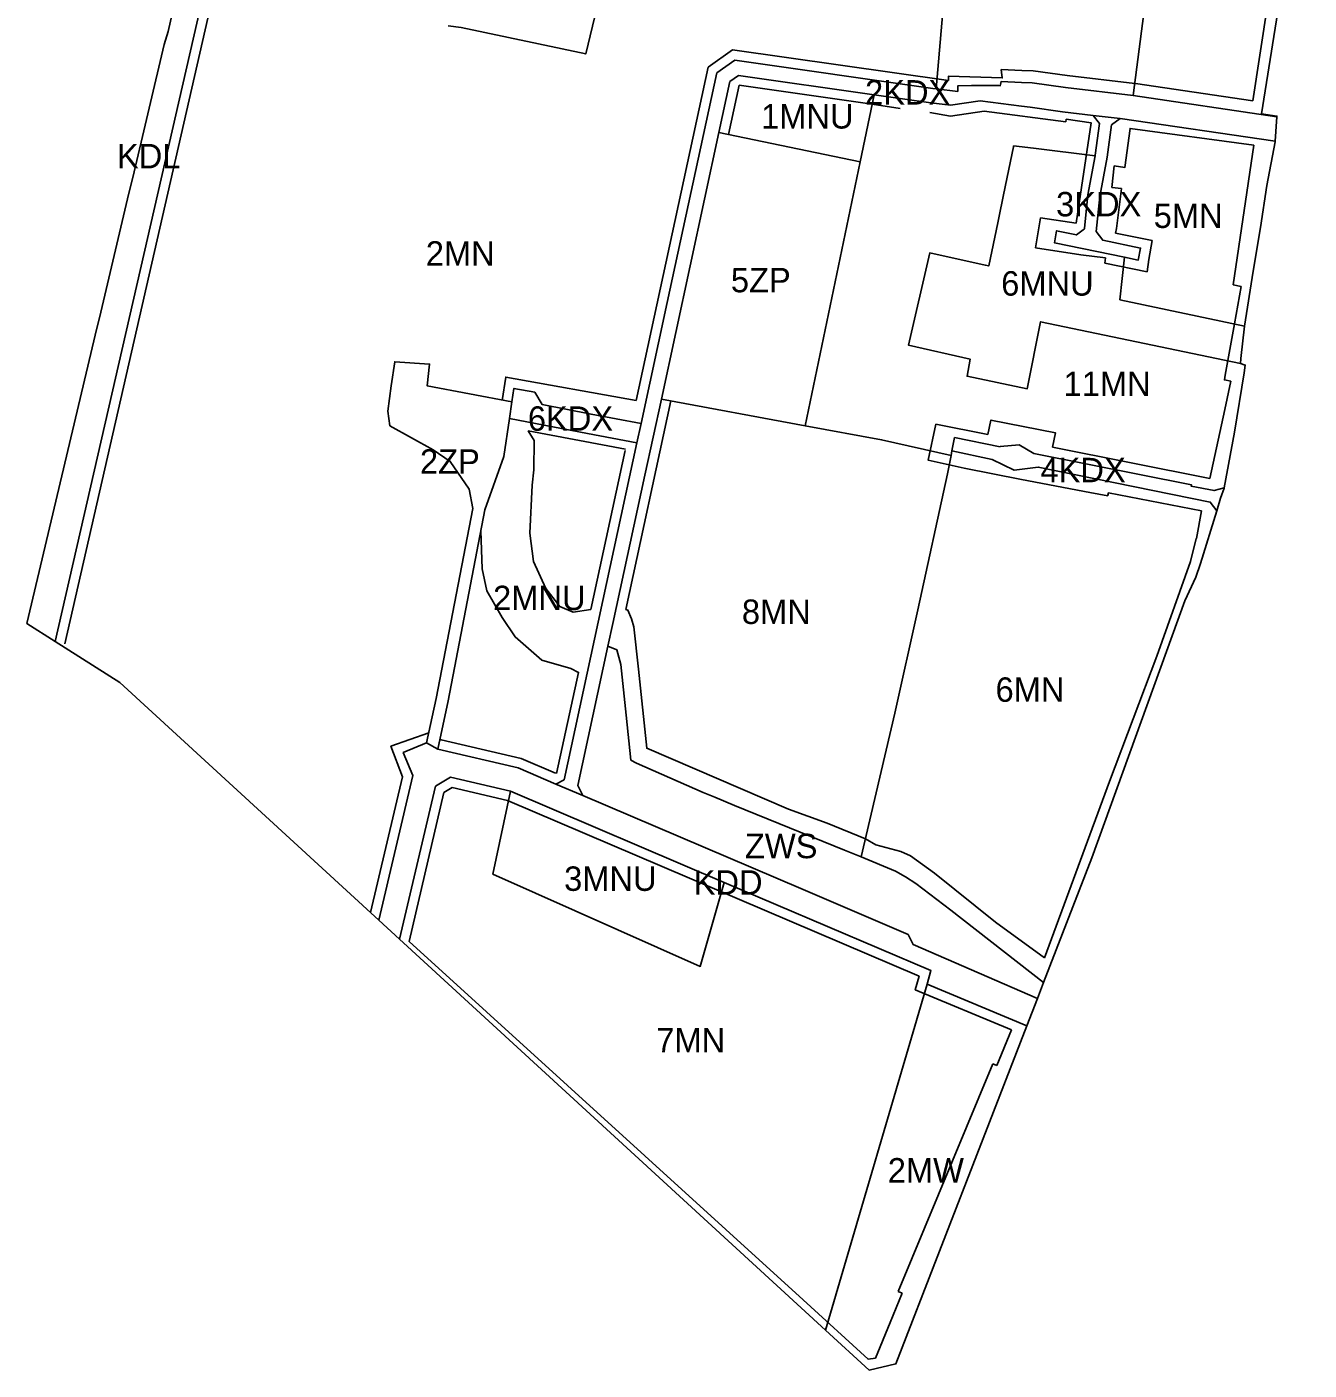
# Model space of a CAD drawing. Extents: x 7419547 to 7422145, y 5541032 to 5541974.
# Drawn here: x 7420351 to 7420876, y 5541032 to 5541582 of the extents above; entities that cross this region are included whole.
import ezdxf

# ---------------------------------------------------------------- set-up
doc = ezdxf.new("R2010")
doc.units = 0
for name, color, linetype in [('linie_rozgraniczajace', 7, 'Continuous'), ('linie_zabudowy_nieprzekraczalne', 7, 'Continuous'), ('oznaczenia_przeznaczen', 7, 'Continuous')]:
    doc.layers.add(name, color=color, linetype=linetype)

msp = doc.modelspace()

# ---------------------------------------------------------------- linework, layer by layer
at = {"layer": 'linie_rozgraniczajace'}
for points in [[(7420734.65, 5541689.59), (7420736.72, 5541689.3), (7420800.6, 5541672.71), (7420818.6, 5541669.11), (7420803.79, 5541554.09), (7420803.78, 5541554.09), (7420776.06, 5541557.45), (7420762.38, 5541559.34), (7420757.99, 5541559.45), (7420749.65, 5541559.87), (7420749.32, 5541558.18), (7420748.75, 5541558.22), (7420737.58, 5541558.22), (7420731.97, 5541558.15), (7420731.89, 5541555.85), (7420723.05, 5541556.92), (7420726.09, 5541591.68), (7420728.7, 5541621.57)], [(7420819.8, 5541678.4), (7420875.82, 5541668.83), (7420874.09, 5541658.03), (7420856.27, 5541546.71), (7420862.63, 5541545.75), (7420862.61, 5541545.48), (7420803.79, 5541554.09), (7420818.6, 5541669.11)], [(7420640.62, 5541568.67), (7420721.7, 5541557.08), (7420723.05, 5541556.92), (7420731.89, 5541555.85), (7420731.97, 5541558.15), (7420737.58, 5541558.22), (7420748.75, 5541558.22), (7420749.32, 5541558.18), (7420749.65, 5541559.87), (7420757.99, 5541559.45), (7420762.38, 5541559.34), (7420776.06, 5541557.45), (7420803.78, 5541554.09), (7420803.79, 5541554.09), (7420862.61, 5541545.48), (7420861.89, 5541535.48), (7420798.37, 5541544.78), (7420787.34, 5541546.01), (7420774.78, 5541547.53), (7420761.56, 5541549.36), (7420758.03, 5541549.77), (7420741.04, 5541552.02), (7420728.98, 5541550.16), (7420720.92, 5541551.13), (7420697.59, 5541554.47), (7420642.13, 5541562.39), (7420638.58, 5541559.88), (7420634.06, 5541538.95), (7420610.47, 5541429.83), (7420603.72, 5541398.61), (7420590.58, 5541337.83), (7420588.59, 5541328.63), (7420576.24, 5541271.46), (7420578.36, 5541267.35), (7420567.22, 5541272.1), (7420570.62, 5541273.86), (7420600.46, 5541411.93), (7420602.15, 5541419.75), (7420612.87, 5541469.33), (7420633.21, 5541563.43)], [(7420642.13, 5541562.39), (7420697.59, 5541554.47), (7420691.91, 5541526.98), (7420634.06, 5541538.95), (7420638.58, 5541559.88)], [(7420697.59, 5541554.47), (7420720.92, 5541551.13), (7420728.98, 5541550.16), (7420741.04, 5541552.02), (7420758.03, 5541549.77), (7420761.56, 5541549.36), (7420774.78, 5541547.53), (7420787.34, 5541546.01), (7420789.91, 5541542.68), (7420788.16, 5541529.73), (7420788.12, 5541529.49), (7420762.87, 5541532.52), (7420754.78, 5541533.48), (7420754.71, 5541533.12), (7420751.45, 5541517.47), (7420749.08, 5541506.07), (7420748.24, 5541502.03), (7420744.56, 5541484.37), (7420743.16, 5541484.68), (7420720.4, 5541489.65), (7420711.69, 5541451.89), (7420736.95, 5541446.16), (7420735.7, 5541439.12), (7420760.34, 5541434.06), (7420765.8, 5541461.49), (7420847.67, 5541444.42), (7420849.68, 5541443.73), (7420849.18, 5541440.56), (7420845.31, 5541416.26), (7420841.08, 5541393.47), (7420836.87, 5541392.29), (7420827.49, 5541394.16), (7420827.64, 5541394.62), (7420762.99, 5541407.51), (7420757.09, 5541411.02), (7420749.25, 5541410.34), (7420749.23, 5541410.25), (7420730.58, 5541414.03), (7420729.53, 5541408.63), (7420729.15, 5541406.72), (7420700.66, 5541413.11), (7420669.4, 5541418.9), (7420691.91, 5541526.98)], [(7420787.34, 5541546.01), (7420798.37, 5541544.78), (7420794.88, 5541542.08), (7420793.1, 5541528.95), (7420790.14, 5541512.76), (7420788.64, 5541498.43), (7420791.27, 5541494.84), (7420806.81, 5541491.64), (7420805.8, 5541486.74), (7420800.14, 5541487.91), (7420771.45, 5541493.82), (7420772.38, 5541498.74), (7420780.47, 5541497.07), (7420783.26, 5541499.11), (7420783.72, 5541499.45), (7420783.74, 5541499.63), (7420785.19, 5541513.47), (7420788.12, 5541529.49), (7420788.16, 5541529.73), (7420789.91, 5541542.68)], [(7420798.37, 5541544.78), (7420861.89, 5541535.48), (7420861.89, 5541535.44), (7420861.87, 5541535.22), (7420858.5, 5541517.3), (7420855.86, 5541500.15), (7420852.9, 5541482.22), (7420849.37, 5541459.72), (7420798.31, 5541470.47), (7420800.14, 5541487.91), (7420805.8, 5541486.74), (7420806.81, 5541491.64), (7420791.27, 5541494.84), (7420788.64, 5541498.43), (7420790.14, 5541512.76), (7420793.1, 5541528.95), (7420794.88, 5541542.08)], [(7420634.06, 5541538.95), (7420691.91, 5541526.98), (7420669.4, 5541418.9), (7420610.47, 5541429.83)], [(7420783.74, 5541499.63), (7420783.72, 5541499.45), (7420783.26, 5541499.11), (7420780.47, 5541497.07), (7420772.38, 5541498.74), (7420771.45, 5541493.82), (7420800.14, 5541487.91), (7420798.31, 5541470.47), (7420849.37, 5541459.72), (7420847.89, 5541446.41), (7420847.67, 5541444.42), (7420765.8, 5541461.49), (7420760.34, 5541434.06), (7420735.7, 5541439.12), (7420736.95, 5541446.16), (7420711.69, 5541451.89), (7420720.4, 5541489.65), (7420743.16, 5541484.68), (7420744.56, 5541484.37), (7420748.24, 5541502.03), (7420749.08, 5541506.07), (7420751.45, 5541517.47), (7420754.71, 5541533.12), (7420754.78, 5541533.48), (7420762.87, 5541532.52), (7420788.12, 5541529.49), (7420785.19, 5541513.47)], [(7420531.82, 5541392.96), (7420524.02, 5541404.24), (7420517.07, 5541409.04), (7420499.2, 5541418.86), (7420498.4, 5541424.9), (7420499.87, 5541435.22), (7420501.28, 5541445.08), (7420515.52, 5541444.16), (7420514.59, 5541435.22), (7420549.28, 5541428.69), (7420548.27, 5541421.78), (7420546, 5541406.31), (7420538.2, 5541384.45), (7420523.2, 5541306.2), (7420518.88, 5541286.38), (7420514.32, 5541288.95), (7420518.3, 5541307.21), (7420533.2, 5541384.96)], [(7420550.08, 5541434.14), (7420558.59, 5541432.62), (7420561.7, 5541427.57), (7420581.7, 5541423.6), (7420602.15, 5541419.75), (7420600.46, 5541411.93), (7420580.22, 5541415.74), (7420548.27, 5541421.78), (7420549.28, 5541428.69)], [(7420610.47, 5541429.83), (7420669.4, 5541418.9), (7420700.66, 5541413.11), (7420729.15, 5541406.72), (7420727.65, 5541399.12), (7420715.58, 5541343.49), (7420706.13, 5541301.09), (7420692.32, 5541242.22), (7420685.46, 5541245.07), (7420640.5, 5541263.37), (7420632.37, 5541266.67), (7420627.59, 5541268.61), (7420600.24, 5541280.68), (7420597.97, 5541281.9), (7420596.02, 5541300.29), (7420594.64, 5541313.34), (7420594.64, 5541313.34), (7420593.83, 5541321.06), (7420592.23, 5541327.11), (7420588.59, 5541328.63), (7420590.58, 5541337.83), (7420603.72, 5541398.61)], [(7420548.27, 5541421.78), (7420580.22, 5541415.74), (7420600.46, 5541411.93), (7420570.62, 5541273.86), (7420567.22, 5541272.1), (7420551.81, 5541278.68), (7420518.88, 5541286.38), (7420523.2, 5541306.2), (7420538.2, 5541384.45), (7420546, 5541406.31)], [(7420730.58, 5541414.03), (7420749.23, 5541410.25), (7420749.25, 5541410.34), (7420757.09, 5541411.02), (7420762.99, 5541407.51), (7420827.64, 5541394.62), (7420827.49, 5541394.16), (7420836.87, 5541392.29), (7420841.08, 5541393.47), (7420841.06, 5541393.36), (7420839.46, 5541389.21), (7420837.97, 5541383.96), (7420835.3, 5541387.58), (7420764.83, 5541401.93), (7420755.01, 5541400.62), (7420745.93, 5541405.06), (7420729.53, 5541408.63)], [(7420729.53, 5541408.63), (7420745.93, 5541405.06), (7420755.01, 5541400.62), (7420764.83, 5541401.93), (7420835.3, 5541387.58), (7420837.97, 5541383.96), (7420831.3, 5541362.47), (7420829.36, 5541356.9), (7420824.9, 5541347.17), (7420786.83, 5541241.86), (7420767.06, 5541190.8), (7420728.99, 5541220.4), (7420714.71, 5541231.31), (7420710.49, 5541234.08), (7420706.35, 5541236.39), (7420692.32, 5541242.22), (7420706.13, 5541301.09), (7420715.58, 5541343.49), (7420727.65, 5541399.12), (7420729.15, 5541406.72)], [(7420588.59, 5541328.63), (7420592.23, 5541327.11), (7420593.83, 5541321.06), (7420594.64, 5541313.34), (7420594.64, 5541313.34), (7420596.02, 5541300.29), (7420597.97, 5541281.9), (7420600.24, 5541280.68), (7420627.59, 5541268.61), (7420632.37, 5541266.67), (7420640.5, 5541263.37), (7420685.46, 5541245.07), (7420692.32, 5541242.22), (7420706.35, 5541236.39), (7420710.49, 5541234.08), (7420714.71, 5541231.31), (7420728.99, 5541220.4), (7420767.06, 5541190.8), (7420764.53, 5541184.26), (7420740.6, 5541194.63), (7420713.61, 5541206.34), (7420711.54, 5541210.53), (7420667.58, 5541229.28), (7420578.36, 5541267.35), (7420576.24, 5541271.46)], [(7420514.32, 5541288.95), (7420518.88, 5541286.38), (7420551.81, 5541278.68), (7420567.22, 5541272.1), (7420578.36, 5541267.35), (7420667.58, 5541229.28), (7420711.54, 5541210.53), (7420713.61, 5541206.34), (7420740.6, 5541194.63), (7420764.53, 5541184.26), (7420760.21, 5541173.11), (7420719.3, 5541190.15), (7420720.91, 5541195.66), (7420636.16, 5541231.82), (7420548.65, 5541269.15), (7420524.1, 5541274.89), (7420517.91, 5541271.21), (7420503.22, 5541208.56), (7420494.76, 5541216.31), (7420508.67, 5541275.63), (7420504.77, 5541284.96)], [(7420524.1, 5541274.89), (7420548.65, 5541269.15), (7420541.45, 5541235.24), (7420626.4, 5541197.41), (7420636.16, 5541231.82), (7420720.91, 5541195.66), (7420719.3, 5541190.15), (7420677.78, 5541048.37), (7420503.22, 5541208.56), (7420517.91, 5541271.21)], [(7420548.65, 5541269.15), (7420636.16, 5541231.82), (7420626.4, 5541197.41), (7420541.45, 5541235.24)], [(7420719.3, 5541190.15), (7420760.21, 5541173.11), (7420706.58, 5541034.58), (7420695.61, 5541032.01), (7420677.78, 5541048.37)]]:
    msp.add_lwpolyline(points, close=True, dxfattribs=at)
for points in [[(7420424.7, 5541603.62), (7420362.21, 5541330.48), (7420350.58, 5541337.88), (7420379.28, 5541458.82), (7420380.3, 5541463.13), (7420392.39, 5541514.09), (7420393.92, 5541520.52), (7420406.87, 5541575.07), (7420408.5, 5541580.32), (7420410.62, 5541590.07)], [(7420726.09, 5541591.68), (7420723.05, 5541556.92), (7420721.7, 5541557.08), (7420640.62, 5541568.67), (7420633.21, 5541563.43), (7420612.87, 5541469.33), (7420602.15, 5541419.75), (7420581.7, 5541423.6), (7420561.7, 5541427.57), (7420558.59, 5541432.62), (7420550.08, 5541434.14), (7420549.28, 5541428.69), (7420514.59, 5541435.22), (7420515.52, 5541444.16), (7420501.28, 5541445.08), (7420499.87, 5541435.22), (7420498.4, 5541424.9), (7420499.2, 5541418.86), (7420517.07, 5541409.04), (7420524.02, 5541404.24), (7420531.82, 5541392.96), (7420533.2, 5541384.96), (7420518.3, 5541307.21), (7420514.32, 5541288.95), (7420504.77, 5541284.96), (7420508.67, 5541275.63), (7420494.76, 5541216.31), (7420388.7, 5541313.64), (7420362.21, 5541330.48), (7420424.7, 5541603.62)], [(7420585, 5541594.08), (7420579.5, 5541571.17), (7420528.54, 5541582), (7420523.09, 5541582.75)], [(7420523.09, 5541582.75), (7420528.54, 5541582), (7420579.5, 5541571.17), (7420585, 5541594.08)]]:
    msp.add_lwpolyline(points, dxfattribs=at)
at = {"layer": 'linie_zabudowy_nieprzekraczalne'}
for points in [[(7420852.74, 5541551.98), (7420870.82, 5541669.68)], [(7420431.32, 5541614.61), (7420366.11, 5541329.59)], [(7420629.63, 5541565.79), (7420639.6, 5541572.85)], [(7420639.6, 5541572.85), (7420728.04, 5541560.34), (7420728.1, 5541562.09), (7420750.13, 5541561.36), (7420749.73, 5541564.87)], [(7420600.11, 5541429.24), (7420629.63, 5541565.79)], [(7420749.73, 5541564.87), (7420758.18, 5541564.45), (7420762.78, 5541564.33), (7420776.71, 5541562.41), (7420804.43, 5541559.05)], [(7420642.36, 5541558.43), (7420637.97, 5541538.14)], [(7420696.78, 5541550.54), (7420642.36, 5541558.43)], [(7420804.63, 5541559.02), (7420852.74, 5541551.98)], [(7420708.3, 5541548.88), (7420696.78, 5541550.54)], [(7420728.85, 5541545.75), (7420720.4, 5541547.17)], [(7420776.17, 5541543.33), (7420742.67, 5541547.77), (7420728.85, 5541545.75)], [(7420765.73, 5541504.1), (7420780.39, 5541501.88), (7420786.57, 5541542.91), (7420776.33, 5541544.44)], [(7420776.17, 5541543.33), (7420776.33, 5541544.44)], [(7420853.12, 5541533.8), (7420802.5, 5541540.65), (7420800.35, 5541524.72), (7420796.02, 5541525.29), (7420795.07, 5541516.49), (7420798.95, 5541516.02), (7420796.94, 5541499.65)], [(7420844.75, 5541476.54), (7420853.12, 5541533.8)], [(7420792.41, 5541487.6), (7420782.34, 5541488.85), (7420763.78, 5541491.78), (7420765.73, 5541504.1)], [(7420796.94, 5541499.65), (7420796.57, 5541497.83), (7420811.53, 5541494.75)], [(7420811.53, 5541494.75), (7420810.12, 5541486.92), (7420809.46, 5541481.86)], [(7420792.15, 5541485.47), (7420792.41, 5541487.6)], [(7420809.46, 5541481.86), (7420792.15, 5541485.47)], [(7420848.02, 5541475.93), (7420844.75, 5541476.54)], [(7420845.26, 5541460.57), (7420848.02, 5541475.93)], [(7420841.44, 5541439.6), (7420845.26, 5541460.57)], [(7420843.69, 5541437.08), (7420841.09, 5541437.65), (7420841.44, 5541439.6)], [(7420545.33, 5541429.27), (7420546.72, 5541438.81), (7420600.11, 5541429.24)], [(7420841.23, 5541425.57), (7420843.69, 5541437.08)], [(7420614.4, 5541429.1), (7420595.93, 5541343.62)], [(7420835.18, 5541397.2), (7420841.23, 5541425.57)], [(7420734.5, 5541401.46), (7420719.78, 5541404.73), (7420722.96, 5541419.57)], [(7420722.96, 5541419.57), (7420744.17, 5541415.34)], [(7420744.17, 5541415.34), (7420745.5, 5541421.21), (7420771.94, 5541415.92), (7420770.76, 5541410.04)], [(7420595.78, 5541409.25), (7420555.97, 5541416.77), (7420558.36, 5541412.82), (7420558.27, 5541400.76), (7420557.54, 5541394.52), (7420556.66, 5541374.9), (7420558.09, 5541363.26), (7420563.13, 5541352.23), (7420568.87, 5541344.77), (7420574.42, 5541342.55), (7420581.6, 5541343.61)], [(7420581.6, 5541343.61), (7420595.68, 5541408.76)], [(7420770.76, 5541410.04), (7420835.18, 5541397.2)], [(7420831.78, 5541384.06), (7420793.59, 5541391.39), (7420793.37, 5541390.44), (7420793.32, 5541390.21), (7420785.96, 5541391.59), (7420758.04, 5541396.92), (7420734.5, 5541401.46)], [(7420829.63, 5541372.71), (7420831.78, 5541384.06)], [(7420567.58, 5541276.4), (7420576.54, 5541317.85), (7420573.35, 5541319.4), (7420561.58, 5541322.8), (7420550.57, 5541332.4), (7420545.22, 5541340.36), (7420539.04, 5541351.31), (7420537.09, 5541360.28), (7420536.55, 5541375.85)], [(7420794.09, 5541273.11), (7420813.44, 5541324.49), (7420827.19, 5541363.29), (7420829.6, 5541372.62)], [(7420595.93, 5541343.62), (7420596.78, 5541343.32), (7420598.22, 5541339.79), (7420599.21, 5541336.53), (7420601.07, 5541319.09), (7420604.52, 5541286.74), (7420662.61, 5541261.82), (7420678.36, 5541256.02), (7420694.15, 5541249.62), (7420698.32, 5541247.19), (7420708.59, 5541244.46), (7420712.55, 5541242.65), (7420722.31, 5541235.58), (7420747.3, 5541215.45), (7420767.41, 5541200.94)], [(7420491.38, 5541219.49), (7420504.5, 5541274.99), (7420499.68, 5541287.55), (7420515.18, 5541293.06)], [(7420519.77, 5541290.47), (7420520.35, 5541290.15)], [(7420520.35, 5541290.15), (7420553.06, 5541282.5)], [(7420553.06, 5541282.5), (7420567.1, 5541276.5)], [(7420521.41, 5541268.64), (7420524.76, 5541270.63)], [(7420547.43, 5541265.33), (7420524.76, 5541270.63)], [(7420767.41, 5541200.94), (7420794.09, 5541273.11)], [(7420521.41, 5541268.64), (7420507.11, 5541207.64)], [(7420753.89, 5541171.41), (7420714.45, 5541187.84), (7420716.08, 5541193.37), (7420547.43, 5541265.33)], [(7420507.11, 5541207.64), (7420668.5, 5541060.75), (7420695.19, 5541036.45), (7420698.17, 5541036.96), (7420704.17, 5541051.57)], [(7420747.86, 5541156.85), (7420753.89, 5541171.41)], [(7420707.46, 5541064.2), (7420746.23, 5541157.52)], [(7420746.23, 5541157.52), (7420747.86, 5541156.85)], [(7420704.17, 5541051.57), (7420709.08, 5541063.54)], [(7420709.08, 5541063.54), (7420707.46, 5541064.2)]]:
    msp.add_lwpolyline(points, dxfattribs=at)

# ---------------------------------------------------------------- texts
at = {"layer": 'oznaczenia_przeznaczen'}
for s, p in [('2KDX', (7420693.91, 5541550.44)), ('1MNU', (7420651.32, 5541540.62)), ('KDL', (7420387.48, 5541524.34)), ('3KDX', (7420772.16, 5541504.64)), ('5MN', (7420812.16, 5541499.9)), ('2MN', (7420513.99, 5541484.46)), ('5ZP', (7420638.95, 5541473.54)), ('6MNU', (7420749.68, 5541472.18)), ('11MN', (7420775.23, 5541431.06)), ('6KDX', (7420555.79, 5541416.82)), ('2ZP', (7420511.59, 5541399.24)), ('4KDX', (7420765.76, 5541395.73)), ('2MNU', (7420541.54, 5541343.34)), ('8MN', (7420643.46, 5541337.69)), ('6MN', (7420747.36, 5541305.79)), ('ZWS', (7420644.71, 5541241.72)), ('3MNU', (7420570.65, 5541228.34)), ('KDD', (7420623.71, 5541226.81)), ('7MN', (7420608.4, 5541162.16)), ('2MW', (7420703.22, 5541108.87))]:
    msp.add_text(s, height=10, dxfattribs=at).set_placement(p)

doc.saveas('drawing.dxf')
